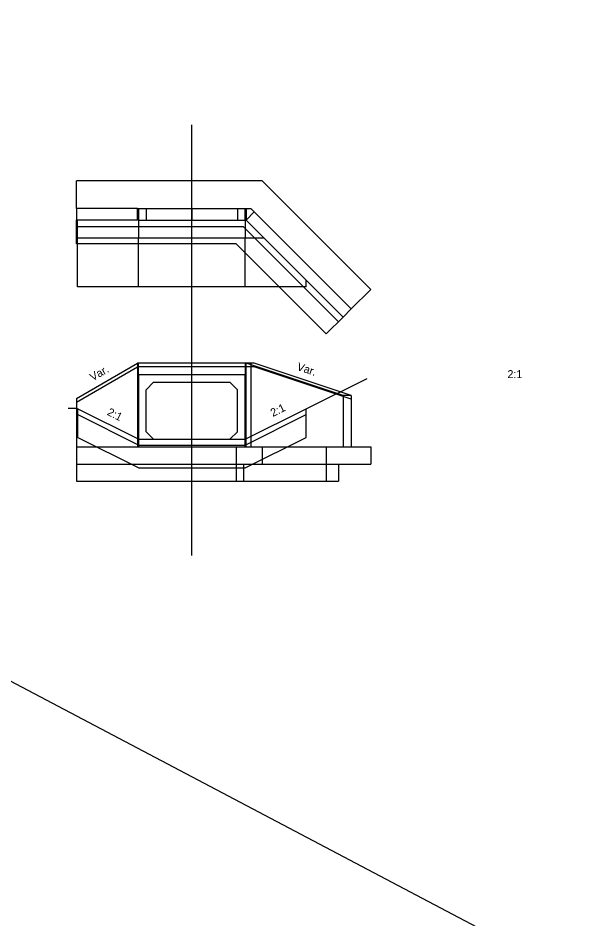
# Model space of a CAD drawing. Extents: x -70 to 515, y 642 to 823.
# Drawn here: x 298 to 346.3, y 744.2 to 823 of the extents above; entities that cross this region are included whole.
import ezdxf

# ---------------------------------------------------------------- set-up
doc = ezdxf.new("R2010")
doc.units = 0
for name, color, linetype in [('DR_P_Culvert', 7, 'Continuous'), ('DR_P_Headwall', 7, 'Continuous'), ('DT_X_Break_Line', 7, 'Continuous'), ('DT_X_Contour_Major', 7, 'Continuous'), ('DT_X_Void', 7, 'Continuous'), ('SH_Major_Grid_Line', 7, 'Continuous'), ('XS_P_Finished_Grade', 7, 'Continuous')]:
    doc.layers.add(name, color=color, linetype=linetype)

msp = doc.modelspace()

# ---------------------------------------------------------------- linework, layer by layer
at = {"layer": 'DR_P_Culvert'}
for p, q in [((309.189, 806.345), (309.189, 805.345)), ((313.189, 806.345), (313.189, 805.345)), ((317.189, 806.345), (317.189, 805.345)), ((303.189, 799.512), (303.189, 805.345)), ((308.522, 799.512), (308.522, 803.762)), ((317.856, 799.512), (317.856, 803.762)), ((323.189, 799.512), (323.189, 800.095)), ((323.188, 799.512), (303.189, 799.512)), ((308.522, 791.826), (308.522, 785.492)), ((317.856, 785.492), (317.856, 791.826)), ((303.189, 788.826), (303.189, 786.326)), ((323.189, 786.326), (323.189, 788.826)), ((308.522, 786.159), (317.856, 786.159))]:
    msp.add_line(p, q, dxfattribs=at)
at = {"layer": 'DR_P_Headwall'}
for p, q in [((308.522, 808.762), (303.106, 808.762)), ((303.106, 806.345), (303.106, 808.762)), ((317.855, 808.762), (308.522, 808.762)), ((319.354, 808.762), (317.855, 808.762)), ((328.84, 799.276), (319.354, 808.762)), ((308.439, 806.345), (303.106, 806.345)), ((303.106, 806.345), (303.106, 805.345)), ((308.522, 806.345), (317.855, 806.345)), ((317.939, 806.345), (318.353, 806.345)), ((327.131, 797.567), (318.353, 806.345)), ((317.939, 805.345), (318.646, 806.053)), ((303.106, 803.262), (303.106, 805.345)), ((308.439, 805.345), (303.106, 805.345)), ((317.697, 804.762), (303.106, 804.762)), ((308.522, 805.345), (308.522, 803.762)), ((308.522, 805.345), (317.855, 805.345)), ((326.012, 796.448), (317.697, 804.762)), ((317.855, 805.345), (317.855, 803.762)), ((326.424, 796.86), (317.939, 805.345)), ((308.522, 803.762), (303.106, 803.762)), ((317.076, 803.262), (303.106, 803.262)), ((317.855, 803.762), (308.522, 803.762)), ((324.951, 795.387), (317.076, 803.262)), ((319.522, 803.762), (317.855, 803.762)), ((328.84, 799.276), (327.131, 797.567)), ((326.424, 796.86), (324.951, 795.387)), ((327.131, 797.567), (326.424, 796.86)), ((303.106, 789.742), (308.438, 792.826)), ((317.856, 792.826), (308.522, 792.826)), ((318.646, 792.826), (317.939, 792.826)), ((326.424, 789.992), (317.939, 792.826)), ((318.353, 792.826), (318.353, 785.492)), ((327.131, 789.992), (318.646, 792.826)), ((308.438, 791.826), (308.438, 785.492)), ((317.939, 785.492), (317.939, 791.826)), ((326.424, 789.992), (326.424, 785.492)), ((327.131, 789.992), (326.424, 789.992)), ((327.131, 789.992), (327.131, 785.492)), ((303.106, 789.742), (303.106, 782.492)), ((303.106, 788.867), (302.399, 788.867)), ((308.522, 786.159), (317.856, 786.159)), ((303.106, 785.492), (308.438, 785.492)), ((317.076, 785.492), (317.076, 782.492)), ((317.939, 785.492), (328.84, 785.492)), ((319.354, 785.492), (319.354, 783.992)), ((324.951, 785.492), (324.951, 782.492)), ((328.84, 785.492), (328.84, 783.992)), ((303.106, 783.992), (326.012, 783.992)), ((317.697, 783.992), (317.697, 782.492)), ((326.012, 783.992), (328.84, 783.992)), ((326.012, 783.992), (326.012, 782.492)), ((303.106, 782.492), (326.012, 782.492))]:
    msp.add_line(p, q, dxfattribs=at)
at = {"layer": 'DT_X_Break_Line'}
for p, q in [((308.522, 791.826), (317.856, 791.826)), ((323.189, 788.826), (328.522, 791.492)), ((309.856, 791.159), (309.189, 790.492)), ((309.856, 791.159), (316.522, 791.159)), ((317.189, 790.492), (316.522, 791.159)), ((309.189, 786.826), (309.189, 790.492)), ((317.189, 786.826), (317.189, 790.492)), ((308.522, 786.159), (303.189, 788.826)), ((308.522, 785.659), (303.189, 788.326)), ((317.856, 786.159), (323.189, 788.826)), ((317.856, 785.659), (323.189, 788.326)), ((309.189, 786.826), (309.856, 786.159)), ((316.522, 786.159), (317.189, 786.826)), ((308.522, 783.659), (303.189, 786.326)), ((309.856, 786.159), (316.522, 786.159)), ((317.856, 783.659), (323.189, 786.326)), ((308.522, 785.659), (317.856, 785.659)), ((308.522, 785.492), (317.856, 785.492)), ((308.522, 783.659), (317.856, 783.659))]:
    msp.add_line(p, q, dxfattribs=at)
at = {"layer": 'DT_X_Void'}
for points in [[(308.522, 806.345), (308.522, 805.345), (308.439, 805.345), (308.439, 806.345)], [(317.939, 806.345), (317.939, 805.345), (317.855, 805.345), (317.855, 806.345)], [(308.438, 785.492), (308.522, 785.492), (308.522, 792.826), (308.438, 792.826)], [(317.856, 785.492), (317.939, 785.492), (317.939, 792.826), (317.856, 792.826)]]:
    msp.add_lwpolyline(points, close=True, dxfattribs=at)
at = {"layer": 'SH_Major_Grid_Line'}
for p, q in [((313.189, 775.999), (313.189, 813.682)), ((308.522, 785.492), (308.522, 791.826)), ((317.856, 785.492), (317.856, 791.826))]:
    msp.add_line(p, q, dxfattribs=at)
at = {"layer": 'XS_P_Finished_Grade'}
for p, q in [((187.231, 823.016), (511.019, 652.405)), ((303.106, 789.409), (308.438, 792.493)), ((318.646, 792.493), (308.438, 792.493)), ((327.131, 789.659), (318.646, 792.493))]:
    msp.add_line(p, q, dxfattribs=at)

# ---------------------------------------------------------------- texts
at = {"layer": 'DT_X_Contour_Major'}
for s, rotation, p in [('Var.', 30.0416, (304.529, 791.225)), ('Var.', 341.53119, (322.32, 792.236)), ('2:1', 26.56505, (320.282, 788.111)), ('2:1', 333.43495, (305.733, 788.318))]:
    msp.add_text(s, height=0.7, rotation=rotation, dxfattribs=at).set_placement(p)
msp.add_text('2:1', height=0.7, dxfattribs=at).set_placement((340.785, 791.512))

doc.saveas('drawing.dxf')
